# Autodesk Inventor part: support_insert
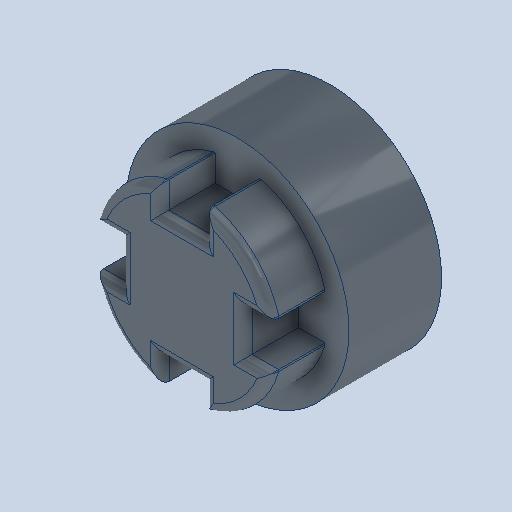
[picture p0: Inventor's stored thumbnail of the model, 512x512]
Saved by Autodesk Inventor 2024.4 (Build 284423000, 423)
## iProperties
Created: 2025-07
Part Number: support_insert
Material: Generic
Document SubType Name: Modeling
Designer: AdminForWorker
Density: 1 g/cm^3
Appearance: Default
Title: support_insert v1
Author: AdminForWorker
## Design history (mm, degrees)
feature "Body1"
body "Solid1"
